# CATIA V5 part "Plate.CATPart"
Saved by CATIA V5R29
Part number: Plate
Source: Unknown
Bounding box of the stored display mesh (mm): x -90 to 90, y -250 to 250, z 0 to 5
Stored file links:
  C:\가치같이\SmartFactory_BoxErectorConveyor\Boxing(over)\Plate.CATPart
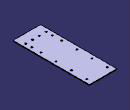
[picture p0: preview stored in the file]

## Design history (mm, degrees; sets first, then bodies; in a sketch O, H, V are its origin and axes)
Body1 (main body)
  Solid1 "PartBody": solid without history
